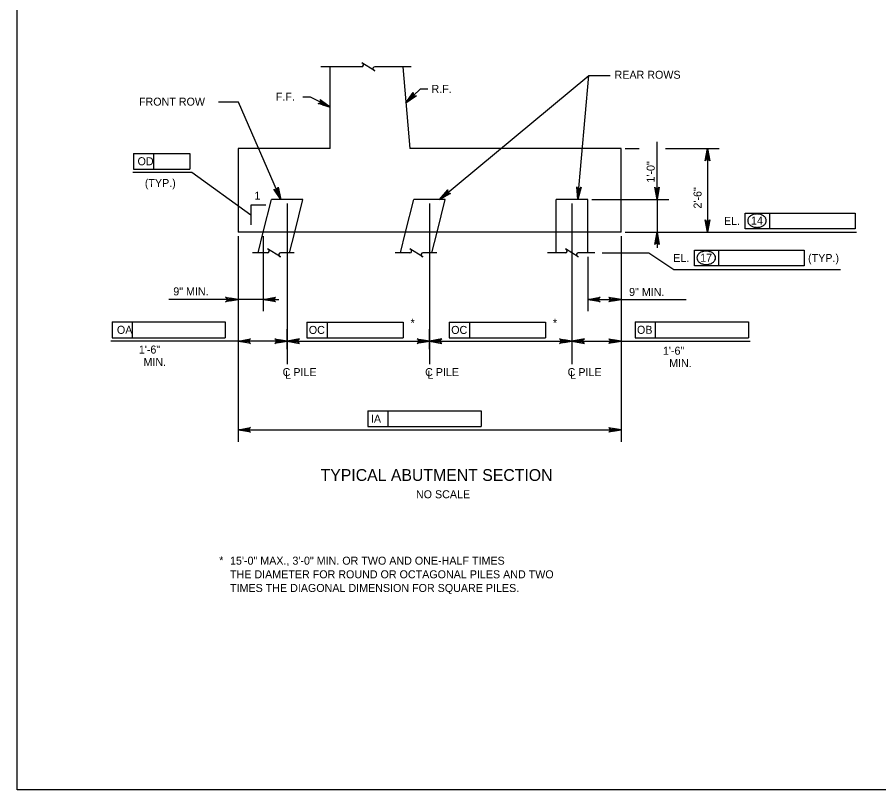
# Model space of a CAD drawing. Extents: x 638340 to 640242, y 295465 to 298435.
# Drawn here: x 639316.5 to 639639.2, y 296074.5 to 296364 of the extents above; entities that cross this region are included whole.
import ezdxf

# ---------------------------------------------------------------- set-up
doc = ezdxf.new("R2010")
doc.units = 0
for name, color, linetype in [('2', 7, 'Continuous'), ('4', 7, 'Continuous'), ('Level 2', 7, 'Continuous'), ('Level 4', 7, 'Continuous'), ('Level 5', 7, 'Continuous')]:
    doc.layers.add(name, color=color, linetype=linetype)

msp = doc.modelspace()

# ---------------------------------------------------------------- linework, layer by layer
at = {"layer": '2'}
for p, q in [((639316.46, 296074.46), (639316.46, 296638.46)), ((640102.46, 296074.46), (639316.46, 296074.46))]:
    msp.add_line(p, q, dxfattribs=at)
at = {"layer": 'Level 2'}
for p, q in [((639530.63, 296342.16), (639538.55, 296342.16)), ((639462.07, 296331.93), (639467.53, 296337.09)), ((639467.53, 296337.09), (639470.25, 296337.09)), ((639399.35, 296332.17), (639391.84, 296332.17)), ((639426.34, 296334.05), (639423.49, 296334.05)), ((639433.68, 296330.24), (639426.34, 296334.05)), ((639556.15, 296295.66), (639556.15, 296317.31)), ((639360.02, 296312.93), (639381.11, 296312.93)), ((639360.02, 296312.93), (639360.02, 296307.04)), ((639367.57, 296312.93), (639367.57, 296307.04)), ((639381.11, 296312.93), (639381.11, 296307.04)), ((639544.24, 296314.82), (639549.45, 296314.82)), ((639559.3, 296314.82), (639579.45, 296314.82)), ((639575.03, 296314.82), (639575.03, 296283.39)), ((639360.02, 296307.04), (639381.11, 296307.04)), ((639381.81, 296305.77), (639359.73, 296305.77)), ((639403.99, 296289.84), (639381.81, 296305.77)), ((639403.99, 296293.58), (639403.99, 296286.1)), ((639409.54, 296293.58), (639403.99, 296293.58)), ((639417.57, 296294.13), (639417.57, 296233.91)), ((639417.57, 296294.13), (639417.57, 296233.91)), ((639470.92, 296294.13), (639470.92, 296233.91)), ((639524.29, 296294.13), (639524.29, 296233.91)), ((639531.72, 296295.66), (639560.57, 296295.66)), ((639556.15, 296295.66), (639556.15, 296283.39)), ((639589.24, 296290.56), (639630.37, 296290.56)), ((639589.24, 296284.66), (639589.24, 296290.56)), ((639598.39, 296284.66), (639598.39, 296290.56)), ((639630.37, 296290.56), (639630.37, 296284.66)), ((639630.37, 296284.66), (639589.24, 296284.66)), ((639399.18, 296281.85), (639399.18, 296204.86)), ((639399.18, 296281.85), (639399.18, 296253.75)), ((639399.18, 296281.85), (639399.18, 296229.56)), ((639408.61, 296281.85), (639408.61, 296253.75)), ((639542.71, 296281.85), (639542.71, 296204.86)), ((639542.71, 296281.85), (639542.71, 296253.75)), ((639542.71, 296281.85), (639542.71, 296229.56)), ((639544.24, 296283.39), (639630.84, 296283.39)), ((639544.24, 296283.39), (639560.57, 296283.39)), ((639556.15, 296283.39), (639556.15, 296277.49)), ((639530.18, 296274.13), (639530.18, 296253.75)), ((639535.66, 296275.67), (639553.1, 296275.67)), ((639553.1, 296275.67), (639562.42, 296269.46)), ((639570.21, 296276.63), (639611.34, 296276.63)), ((639570.21, 296270.74), (639570.21, 296276.63)), ((639579.36, 296270.74), (639579.36, 296276.63)), ((639611.34, 296276.63), (639611.34, 296270.74)), ((639562.42, 296269.46), (639624.85, 296269.46)), ((639611.34, 296270.74), (639570.21, 296270.74)), ((639408.61, 296258.17), (639373.22, 296258.17)), ((639408.61, 296258.17), (639414.5, 296258.17)), ((639530.18, 296258.17), (639542.71, 296258.17)), ((639542.71, 296258.17), (639567.11, 296258.17)), ((639351.98, 296249.77), (639394.42, 296249.77)), ((639351.98, 296249.77), (639351.98, 296243.87)), ((639359.53, 296249.77), (639359.53, 296243.87)), ((639394.42, 296249.77), (639394.42, 296243.87)), ((639424.98, 296249.72), (639461.04, 296249.72)), ((639424.98, 296249.72), (639424.98, 296243.83)), ((639432.53, 296249.72), (639432.53, 296243.83)), ((639461.04, 296249.72), (639461.04, 296243.83)), ((639478.33, 296249.72), (639514.39, 296249.72)), ((639478.33, 296249.72), (639478.33, 296243.83)), ((639485.87, 296249.72), (639485.87, 296243.83)), ((639514.39, 296249.72), (639514.39, 296243.83)), ((639542.71, 296251.11), (639542.71, 296231.02)), ((639547.93, 296249.77), (639590.37, 296249.77)), ((639547.93, 296249.77), (639547.93, 296243.87)), ((639555.47, 296249.77), (639555.47, 296243.87)), ((639590.37, 296249.77), (639590.37, 296243.87)), ((639417.57, 296239.58), (639417.57, 296247.02)), ((639470.92, 296239.58), (639470.92, 296247.02)), ((639399.18, 296242.6), (639351.57, 296242.6)), ((639351.98, 296243.87), (639394.42, 296243.87)), ((639414.63, 296242.6), (639399.18, 296242.6)), ((639420.52, 296242.6), (639467.97, 296242.6)), ((639424.98, 296243.83), (639461.04, 296243.83)), ((639473.86, 296242.6), (639521.31, 296242.6)), ((639478.33, 296243.83), (639514.39, 296243.83)), ((639527.23, 296242.6), (639542.71, 296242.6)), ((639542.71, 296242.6), (639591.01, 296242.6)), ((639547.93, 296243.87), (639590.37, 296243.87)), ((639447.77, 296216.45), (639490.21, 296216.45)), ((639447.77, 296216.45), (639447.77, 296210.56)), ((639455.31, 296216.45), (639455.31, 296210.56)), ((639490.21, 296216.45), (639490.21, 296210.56)), ((639447.77, 296210.56), (639490.21, 296210.56)), ((639399.18, 296209.29), (639542.71, 296209.29))]:
    msp.add_line(p, q, dxfattribs=at)
for points in [[(639474.7, 296295.66), (639530.63, 296342.16)], [(639526.51, 296295.66), (639530.63, 296342.16)], [(639462.07, 296331.93), (639464.85, 296335.76), (639464.76, 296335.34), (639464.84, 296334.98), (639465.02, 296334.72), (639465.27, 296334.53), (639465.62, 296334.43), (639466.05, 296334.49), (639462.07, 296331.93), (639465.62, 296334.43), (639465.27, 296334.53), (639462.07, 296331.93), (639465.02, 296334.72), (639464.84, 296334.98), (639462.07, 296331.93), (639464.76, 296335.34)], [(639415.24, 296295.66), (639399.35, 296332.17)], [(639433.68, 296330.24), (639429.15, 296331.61), (639429.58, 296331.67), (639429.89, 296331.86), (639430.08, 296332.11), (639430.18, 296332.41), (639430.16, 296332.77), (639429.95, 296333.16), (639433.68, 296330.24), (639430.16, 296332.77), (639430.18, 296332.41), (639433.68, 296330.24), (639430.08, 296332.11), (639429.89, 296331.86), (639433.68, 296330.24), (639429.58, 296331.67)], [(639575.03, 296314.82), (639575.9, 296310.17), (639575.65, 296310.53), (639575.34, 296310.71), (639575.03, 296310.77), (639574.72, 296310.71), (639574.4, 296310.53), (639574.16, 296310.17), (639575.03, 296314.82), (639574.4, 296310.53), (639574.72, 296310.71), (639575.03, 296314.82), (639575.03, 296310.77), (639575.34, 296310.71), (639575.03, 296314.82), (639575.65, 296310.53)], [(639415.24, 296295.66), (639412.58, 296299.58), (639412.95, 296299.35), (639413.31, 296299.3), (639413.62, 296299.38), (639413.88, 296299.55), (639414.09, 296299.85), (639414.18, 296300.27), (639415.24, 296295.66), (639414.09, 296299.85), (639413.88, 296299.55), (639415.24, 296295.66), (639413.62, 296299.38), (639413.31, 296299.3), (639415.24, 296295.66), (639412.95, 296299.35)], [(639526.51, 296295.66), (639526.05, 296300.37), (639526.27, 296299.99), (639526.56, 296299.78), (639526.87, 296299.7), (639527.18, 296299.73), (639527.51, 296299.88), (639527.79, 296300.22), (639526.51, 296295.66), (639527.51, 296299.88), (639527.18, 296299.73), (639526.51, 296295.66), (639526.87, 296299.7), (639526.56, 296299.78), (639526.51, 296295.66), (639526.27, 296299.99)], [(639556.15, 296295.66), (639555.28, 296300.31), (639555.52, 296299.95), (639555.83, 296299.77), (639556.15, 296299.71), (639556.46, 296299.77), (639556.77, 296299.95), (639557.02, 296300.31), (639556.15, 296295.66), (639556.77, 296299.95), (639556.46, 296299.77), (639556.15, 296295.66), (639556.15, 296299.71), (639555.83, 296299.77), (639556.15, 296295.66), (639555.52, 296299.95)], [(639474.7, 296295.66), (639477.72, 296299.31), (639477.6, 296298.89), (639477.66, 296298.53), (639477.82, 296298.25), (639478.06, 296298.05), (639478.4, 296297.92), (639478.83, 296297.96), (639474.7, 296295.66), (639478.4, 296297.92), (639478.06, 296298.05), (639474.7, 296295.66), (639477.82, 296298.25), (639477.66, 296298.53), (639474.7, 296295.66), (639477.6, 296298.89)], [(639575.03, 296283.39), (639574.16, 296288.04), (639574.4, 296287.68), (639574.72, 296287.49), (639575.03, 296287.44), (639575.34, 296287.49), (639575.65, 296287.68), (639575.9, 296288.04), (639575.03, 296283.39), (639575.65, 296287.68), (639575.34, 296287.49), (639575.03, 296283.39), (639575.03, 296287.44), (639574.72, 296287.49), (639575.03, 296283.39), (639574.4, 296287.68)], [(639556.15, 296283.39), (639557.02, 296278.73), (639556.77, 296279.09), (639556.46, 296279.28), (639556.15, 296279.33), (639555.83, 296279.28), (639555.52, 296279.09), (639555.28, 296278.73), (639556.15, 296283.39), (639555.52, 296279.09), (639555.83, 296279.28), (639556.15, 296283.39), (639556.15, 296279.33), (639556.46, 296279.28), (639556.15, 296283.39), (639556.77, 296279.09)], [(639399.18, 296258.17), (639394.53, 296257.3), (639394.89, 296257.55), (639395.07, 296257.86), (639395.12, 296258.17), (639395.07, 296258.48), (639394.89, 296258.79), (639394.53, 296259.04), (639399.18, 296258.17), (639394.89, 296258.79), (639395.07, 296258.48), (639399.18, 296258.17), (639395.12, 296258.17), (639395.07, 296257.86), (639399.18, 296258.17), (639394.89, 296257.55)], [(639408.61, 296258.17), (639413.26, 296259.04), (639412.91, 296258.79), (639412.72, 296258.48), (639412.67, 296258.17), (639412.72, 296257.86), (639412.91, 296257.55), (639413.26, 296257.3), (639408.61, 296258.17), (639412.91, 296257.55), (639412.72, 296257.86), (639408.61, 296258.17), (639412.67, 296258.17), (639412.72, 296258.48), (639408.61, 296258.17), (639412.91, 296258.79)], [(639530.18, 296258.17), (639534.83, 296259.04), (639534.48, 296258.79), (639534.29, 296258.48), (639534.24, 296258.17), (639534.29, 296257.86), (639534.48, 296257.55), (639534.83, 296257.3), (639530.18, 296258.17), (639534.48, 296257.55), (639534.29, 296257.86), (639530.18, 296258.17), (639534.24, 296258.17), (639534.29, 296258.48), (639530.18, 296258.17), (639534.48, 296258.79)], [(639542.71, 296258.17), (639538.05, 296257.3), (639538.41, 296257.55), (639538.6, 296257.86), (639538.65, 296258.17), (639538.6, 296258.48), (639538.41, 296258.79), (639538.05, 296259.04), (639542.71, 296258.17), (639538.41, 296258.79), (639538.6, 296258.48), (639542.71, 296258.17), (639538.65, 296258.17), (639538.6, 296257.86), (639542.71, 296258.17), (639538.41, 296257.55)], [(639399.18, 296242.6), (639403.83, 296243.47), (639403.47, 296243.22), (639403.29, 296242.91), (639403.23, 296242.6), (639403.29, 296242.29), (639403.47, 296241.98), (639403.83, 296241.73), (639399.18, 296242.6), (639403.47, 296241.98), (639403.29, 296242.29), (639399.18, 296242.6), (639403.23, 296242.6), (639403.29, 296242.91), (639399.18, 296242.6), (639403.47, 296243.22)], [(639417.57, 296242.6), (639412.92, 296241.73), (639413.28, 296241.98), (639413.46, 296242.29), (639413.52, 296242.6), (639413.46, 296242.91), (639413.28, 296243.22), (639412.92, 296243.47), (639417.57, 296242.6), (639413.28, 296243.22), (639413.46, 296242.91), (639417.57, 296242.6), (639413.52, 296242.6), (639413.46, 296242.29), (639417.57, 296242.6), (639413.28, 296241.98)], [(639417.57, 296242.6), (639422.22, 296241.73), (639421.87, 296241.98), (639421.68, 296242.29), (639421.63, 296242.6), (639421.68, 296242.91), (639421.87, 296243.22), (639422.22, 296243.47), (639417.57, 296242.6), (639421.87, 296243.22), (639421.68, 296242.91), (639417.57, 296242.6), (639421.63, 296242.6), (639421.68, 296242.29), (639417.57, 296242.6), (639421.87, 296241.98)], [(639470.92, 296242.6), (639466.27, 296241.73), (639466.62, 296241.98), (639466.81, 296242.29), (639466.86, 296242.6), (639466.81, 296242.91), (639466.62, 296243.22), (639466.27, 296243.47), (639470.92, 296242.6), (639466.62, 296243.22), (639466.81, 296242.91), (639470.92, 296242.6), (639466.86, 296242.6), (639466.81, 296242.29), (639470.92, 296242.6), (639466.62, 296241.98)], [(639470.92, 296242.6), (639475.57, 296241.73), (639475.21, 296241.98), (639475.03, 296242.29), (639474.97, 296242.6), (639475.03, 296242.91), (639475.21, 296243.22), (639475.57, 296243.47), (639470.92, 296242.6), (639475.21, 296243.22), (639475.03, 296242.91), (639470.92, 296242.6), (639474.97, 296242.6), (639475.03, 296242.29), (639470.92, 296242.6), (639475.21, 296241.98)], [(639524.29, 296242.6), (639519.63, 296241.73), (639519.99, 296241.98), (639520.18, 296242.29), (639520.23, 296242.6), (639520.18, 296242.91), (639519.99, 296243.22), (639519.63, 296243.47), (639524.29, 296242.6), (639519.99, 296243.22), (639520.18, 296242.91), (639524.29, 296242.6), (639520.23, 296242.6), (639520.18, 296242.29), (639524.29, 296242.6), (639519.99, 296241.98)], [(639524.29, 296242.6), (639528.94, 296241.73), (639528.58, 296241.98), (639528.4, 296242.29), (639528.34, 296242.6), (639528.4, 296242.91), (639528.58, 296243.22), (639528.94, 296243.47), (639524.29, 296242.6), (639528.58, 296243.22), (639528.4, 296242.91), (639524.29, 296242.6), (639528.34, 296242.6), (639528.4, 296242.29), (639524.29, 296242.6), (639528.58, 296241.98)], [(639542.71, 296242.6), (639538.05, 296241.73), (639538.41, 296241.98), (639538.6, 296242.29), (639538.65, 296242.6), (639538.6, 296242.91), (639538.41, 296243.22), (639538.05, 296243.47), (639542.71, 296242.6), (639538.41, 296243.22), (639538.6, 296242.91), (639542.71, 296242.6), (639538.65, 296242.6), (639538.6, 296242.29), (639542.71, 296242.6), (639538.41, 296241.98)], [(639399.18, 296209.29), (639403.83, 296210.16), (639403.47, 296209.91), (639403.29, 296209.6), (639403.23, 296209.29), (639403.29, 296208.97), (639403.47, 296208.66), (639403.83, 296208.41), (639399.18, 296209.29), (639403.47, 296208.66), (639403.29, 296208.97), (639399.18, 296209.29), (639403.23, 296209.29), (639403.29, 296209.6), (639399.18, 296209.29), (639403.47, 296209.91)], [(639542.71, 296209.29), (639538.05, 296208.41), (639538.41, 296208.66), (639538.6, 296208.97), (639538.65, 296209.29), (639538.6, 296209.6), (639538.41, 296209.91), (639538.05, 296210.16), (639542.71, 296209.29), (639538.41, 296209.91), (639538.6, 296209.6), (639542.71, 296209.29), (639538.65, 296209.29), (639538.6, 296208.97), (639542.71, 296209.29), (639538.41, 296208.66)]]:
    msp.add_lwpolyline(points, dxfattribs=at)
for points in [[(639464.55, 296333.6), (639463.87, 296334.32), (639462.07, 296331.93)], [(639431.29, 296332.04), (639430.84, 296331.16), (639433.68, 296330.24)], [(639574.54, 296311.88), (639575.52, 296311.88), (639575.03, 296314.82)], [(639415.24, 296295.66), (639414.28, 296298.46), (639413.83, 296298.27)], [(639474.7, 296295.66), (639477.12, 296297.36), (639476.81, 296297.73)], [(639526.51, 296295.66), (639526.83, 296298.6), (639526.34, 296298.61)], [(639555.66, 296298.61), (639556.64, 296298.61), (639556.15, 296295.66)], [(639574.54, 296286.33), (639575.52, 296286.33), (639575.03, 296283.39)], [(639555.66, 296280.44), (639556.64, 296280.44), (639556.15, 296283.39)], [(639396.23, 296258.66), (639396.23, 296257.68), (639399.18, 296258.17)], [(639411.56, 296258.66), (639411.56, 296257.68), (639408.61, 296258.17)], [(639533.13, 296258.66), (639533.13, 296257.68), (639530.18, 296258.17)], [(639539.76, 296258.66), (639539.76, 296257.68), (639542.71, 296258.17)], [(639414.63, 296243.09), (639414.63, 296242.11), (639417.57, 296242.6)], [(639420.52, 296243.09), (639420.52, 296242.11), (639417.57, 296242.6)], [(639467.97, 296243.09), (639467.97, 296242.11), (639470.92, 296242.6)], [(639473.86, 296243.09), (639473.86, 296242.11), (639470.92, 296242.6)], [(639521.31, 296243.09), (639521.31, 296242.11), (639524.26, 296242.6)], [(639527.23, 296243.09), (639527.23, 296242.11), (639524.29, 296242.6)], [(639539.76, 296243.09), (639539.76, 296242.11), (639542.71, 296242.6)], [(639402.13, 296209.78), (639402.13, 296208.79), (639399.18, 296209.29)], [(639539.76, 296209.78), (639539.76, 296208.79), (639542.71, 296209.29)]]:
    msp.add_lwpolyline(points, close=True, dxfattribs=at)
for centre, radius, start, end in [((639593.61, 296285.36), 4.86, 90, 106.5358), ((639593.61, 296285.36), 4.86, 73.4642, 90), ((639591.94, 296287.72), 1.82, 149.9767, 180), ((639591.94, 296287.72), 1.82, 180, 210.0233), ((639592.74, 296287.25), 2.75, 125.6316, 149.9767), ((639593.27, 296286.52), 3.65, 106.5358, 125.6316), ((639593.95, 296286.52), 3.65, 54.3684, 73.4642), ((639594.48, 296287.25), 2.75, 30.0233, 54.3684), ((639595.28, 296287.72), 1.82, 0, 30.0233), ((639595.28, 296287.72), 1.82, 329.9767, 0), ((639592.74, 296288.18), 2.75, 210.0233, 234.3684), ((639593.27, 296288.92), 3.65, 234.3684, 253.4642), ((639593.61, 296290.08), 4.86, 253.4642, 270), ((639593.61, 296290.08), 4.86, 270, 286.5358), ((639593.95, 296288.92), 3.65, 286.5358, 305.6316), ((639594.48, 296288.18), 2.75, 305.6316, 329.9767), ((639572.9, 296273.79), 1.82, 149.9767, 180), ((639573.71, 296273.33), 2.75, 125.6316, 149.9767), ((639574.23, 296272.6), 3.65, 106.5358, 125.6316), ((639574.58, 296271.44), 4.86, 90, 106.5358), ((639574.58, 296271.44), 4.86, 73.4642, 90), ((639574.92, 296272.6), 3.65, 54.3684, 73.4642), ((639575.45, 296273.33), 2.75, 30.0233, 54.3684), ((639576.25, 296273.79), 1.82, 0, 30.0233), ((639572.9, 296273.79), 1.82, 180, 210.0233), ((639573.71, 296274.26), 2.75, 210.0233, 234.3684), ((639574.23, 296274.99), 3.65, 234.3684, 253.4642), ((639574.58, 296276.15), 4.86, 253.4642, 270), ((639574.58, 296276.15), 4.86, 270, 286.5358), ((639574.92, 296274.99), 3.65, 286.5358, 305.6316), ((639575.45, 296274.26), 2.75, 305.6316, 329.9767), ((639576.25, 296273.79), 1.82, 329.9767, 0)]:
    msp.add_arc(centre, radius, start, end, dxfattribs=at)
at = {"layer": 'Level 4'}
for p, q in [((639445.59, 296345.39), (639430.16, 296345.39)), ((639433.68, 296314.82), (639433.68, 296345.39)), ((639464.08, 296345.39), (639450.43, 296345.39)), ((639460.95, 296345.39), (639463.5, 296314.82)), ((639399.18, 296314.82), (639399.18, 296283.39)), ((639433.68, 296314.82), (639399.18, 296314.82)), ((639542.71, 296314.82), (639463.5, 296314.82)), ((639542.71, 296283.39), (639542.71, 296314.82)), ((639542.71, 296283.39), (639399.18, 296283.39))]:
    msp.add_line(p, q, dxfattribs=at)
msp.add_lwpolyline([(639450.08, 296344.07), (639450.38, 296343.88), (639445.58, 296346.9), (639445.9, 296346.7)], dxfattribs=at)
for centre, start, end in [((639445.52, 296346.1), 275.3286, 57.8672), ((639450.43, 296344.68), 90, 240)]:
    msp.add_arc(centre, 0.709, start, end, dxfattribs=at)
at = {"layer": 'Level 5'}
for p, q in [((639408.61, 296283.39), (639411.68, 296295.66)), ((639423.47, 296295.66), (639411.68, 296295.66)), ((639420.4, 296283.39), (639423.47, 296295.66)), ((639461.96, 296283.39), (639465.02, 296295.66)), ((639476.81, 296295.66), (639465.02, 296295.66)), ((639473.74, 296283.39), (639476.81, 296295.66)), ((639518.39, 296283.39), (639518.39, 296295.66)), ((639530.18, 296295.66), (639518.39, 296295.66)), ((639530.18, 296283.39), (639530.18, 296295.66)), ((639406.68, 296275.67), (639408.61, 296283.39)), ((639418.47, 296275.67), (639420.4, 296283.39)), ((639460.03, 296275.67), (639461.96, 296283.39)), ((639471.81, 296275.67), (639473.74, 296283.39)), ((639518.39, 296275.67), (639518.39, 296283.39)), ((639530.18, 296275.67), (639530.18, 296283.39)), ((639410.25, 296275.67), (639404.66, 296275.67)), ((639420.27, 296275.67), (639415.1, 296275.67)), ((639463.59, 296275.67), (639458, 296275.67)), ((639473.62, 296275.67), (639468.44, 296275.67)), ((639521.82, 296275.67), (639515.1, 296275.67)), ((639532.8, 296275.67), (639526.67, 296275.67))]:
    msp.add_line(p, q, dxfattribs=at)
for points in [[(639414.74, 296274.34), (639415.04, 296274.16), (639410.24, 296277.18), (639410.56, 296276.98)], [(639468.09, 296274.34), (639468.38, 296274.16), (639463.58, 296277.18), (639463.9, 296276.98)], [(639526.32, 296274.34), (639526.62, 296274.16), (639521.81, 296277.18), (639522.13, 296276.98)]]:
    msp.add_lwpolyline(points, dxfattribs=at)
for centre, start, end in [((639410.18, 296276.37), 275.3286, 57.8672), ((639415.1, 296274.96), 90, 240), ((639463.53, 296276.37), 275.3286, 57.8672), ((639468.44, 296274.96), 90, 240), ((639521.76, 296276.37), 275.3286, 57.8672), ((639526.67, 296274.96), 90, 240)]:
    msp.add_arc(centre, 0.709, start, end, dxfattribs=at)

# ---------------------------------------------------------------- texts
at = {"layer": '2'}
msp.add_text('NO SCALE', height=3, dxfattribs=at).set_placement((639465.84, 296183.69))
at = {"layer": '4'}
msp.add_text('TYPICAL ABUTMENT SECTION', height=4.4294, dxfattribs=at).set_placement((639430.11, 296190.19))
at = {"layer": 'Level 2'}
for s, height, p in [('REAR ROWS', 3, (639540.25, 296340.9)), ('R.F.', 3, (639471.66, 296335.6)), ('F.F.', 3, (639413.33, 296332.69)), ('FRONT ROW', 3, (639362.07, 296330.82)), ('1', 3, (639405.32, 296295.62)), ('EL.', 3, (639581.24, 296286.15)), ('14', 3, (639591.37, 296286.26)), ('EL.', 3, (639562.21, 296272.22)), ('17', 3, (639572.32, 296272.33)), ('(TYP.)', 3, (639612.75, 296272.22)), ('9" MIN.', 3, (639374.93, 296259.72)), ('9" MIN.', 3, (639545.69, 296259.5)), ('1\'-6"', 3, (639362.01, 296237.92)), ('1\'-6"', 3, (639558.37, 296237.48)), ('MIN.', 3, (639363.75, 296233.27)), ('MIN.', 3, (639560.7, 296232.83)), ('C PILE', 3, (639415.89, 296229.47)), ('C PILE', 3, (639469.27, 296229.47)), ('C PILE', 3, (639522.66, 296229.47)), ('L', 3, (639416.77, 296228.45)), ('L', 3, (639470.16, 296228.45)), ('L', 3, (639523.54, 296228.45)), ('15\'-0" MAX., 3\'-0" MIN. OR TWO AND ONE-HALF TIMES', 3.0001, (639396.18, 296158.81)), ('THE DIAMETER FOR ROUND OR OCTAGONAL PILES AND TWO', 3.0001, (639396.18, 296153.7)), ('TIMES THE DIAGONAL DIMENSION FOR SQUARE PILES.', 3.0001, (639396.18, 296148.58))]:
    msp.add_text(s, height=height, dxfattribs=at).set_placement(p)
for s, rotation, p in [('OD', 359.9382, (639361.53, 296308.49)), ('1\'-0"', 90, (639555.28, 296302)), ('(TYP.)', 359.9382, (639364.26, 296300.35)), ('2\'-6"', 90, (639572.85, 296292.26)), ('OA', 359.9382, (639353.8, 296245.32)), ('OC', 359.9382, (639425.7, 296245.28)), ('*', 359.9382, (639463.82, 296247.95)), ('OC', 359.9382, (639479.04, 296245.28)), ('*', 359.9382, (639517.16, 296247.95)), ('OB', 359.9382, (639548.65, 296245.32)), ('IA', 359.9382, (639448.97, 296212.01)), ('*', 359.9382, (639392.13, 296158.97))]:
    msp.add_text(s, height=3, rotation=rotation, dxfattribs=at).set_placement(p)

doc.saveas('drawing.dxf')
